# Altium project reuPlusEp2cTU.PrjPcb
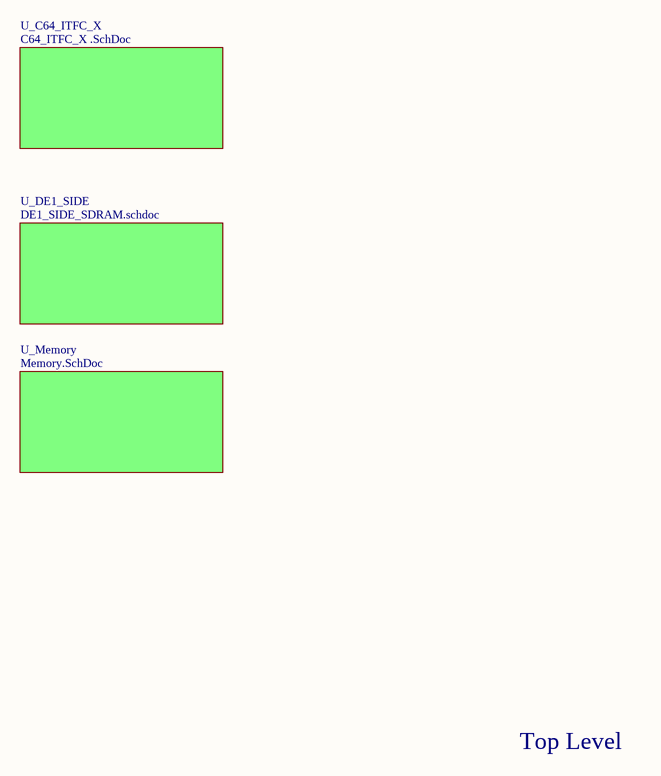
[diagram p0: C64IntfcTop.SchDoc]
4 sheets, 67 parts. Net scope: global (net labels, ports and power ports of the same name join across sheets).
Sheets:
  C64IntfcTop.SchDoc
    U_DE1_SIDE = DE1_SIDE_SDRAM.schdoc
    U_C64_ITFC_X = C64_ITFC_X .SchDoc
    U_Memory = Memory.SchDoc

## Sheet C64IntfcTop.SchDoc
size A; SheetNumber: 1; SheetTotal: 4

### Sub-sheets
U_C64_ITFC_X = C64_ITFC_X .SchDoc: no entries
U_DE1_SIDE = DE1_SIDE_SDRAM.schdoc: no entries
U_Memory = Memory.SchDoc: no entries

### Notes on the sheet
- Top Level

## Sheet DE1_SIDE_SDRAM.schdoc
size B; SheetNumber: 3; SheetTotal: 4
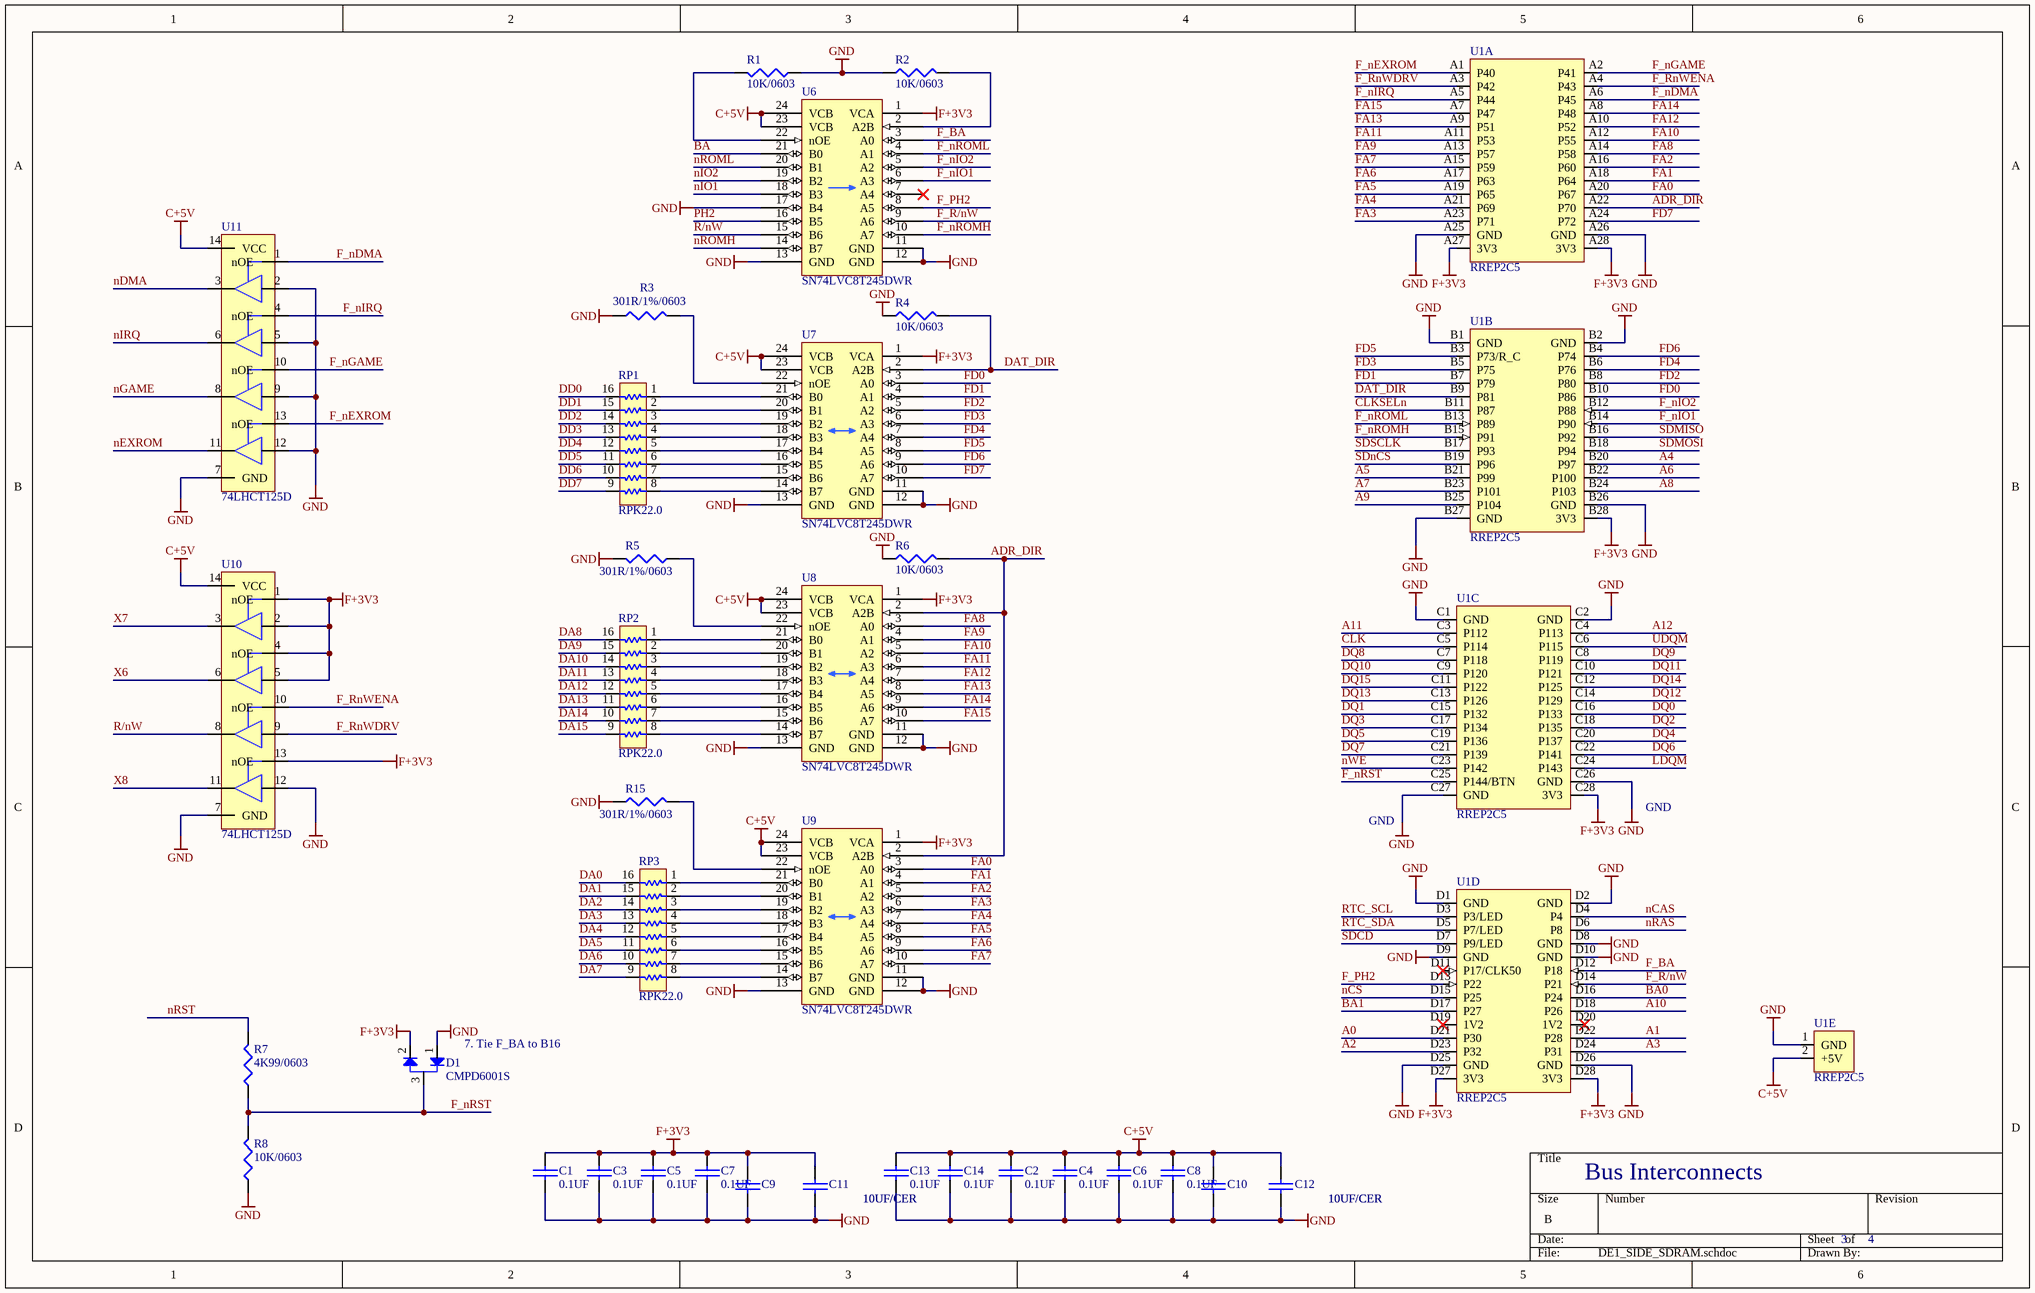
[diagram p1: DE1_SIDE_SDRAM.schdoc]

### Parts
C1  0.1UF  [0603]
C2  0.1UF  [0603]
C3  0.1UF  [0603]
C4  0.1UF  [0603]
C5  0.1UF  [0603]
C6  0.1UF  [0603]
C7  0.1UF  [0603]
C8  0.1UF  [0603]
C9  10UF/CER  [0805]
C10  10UF/CER  [0805]
C11  10UF/CER  [0805]
C12  10UF/CER  [0805]
C13  0.1UF  [0603]
C14  0.1UF  [0603]
D1  CMPD6001S  [SOT-23]
R1  10K/0603  [0603]
R2  10K/0603  [0603]
R3  301R/1%/0603  [0603]
R4  10K/0603  [0603]
R5  301R/1%/0603  [0603]
R6  10K/0603  [0603]
R7  4K99/0603  [0603]
R8  10K/0603  [0603]
R15  301R/1%/0603  [0603]
RP1  RPK22.0  [RPK4816]
RP2  RPK22.0  [RPK4816]
RP3  RPK22.0  [RPK4816]
U1  RREP2C5  [RR2C5]  (parts A,B,C,D,E of 5)
U6  SN74LVC8T245DWR  [SOL-24]
U7  SN74LVC8T245DWR  [SOL-24]
U8  SN74LVC8T245DWR  [SOL-24]
U9  SN74LVC8T245DWR  [SOL-24]
U10  74LHCT125D  [SOP14]
U11  74LHCT125D  [SOP14]

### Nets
C+5V: C2.1 C4.1 C6.1 C8.1 C10.2 C12.2 C13.1 C14.1 U1.2(+5V) U6.23(VCB) U6.24(VCB) U7.23(VCB) U7.24(VCB) U8.23(VCB) U8.24(VCB) U9.23(VCB) U9.24(VCB) U10.14(VCC) U11.14(VCC)
F+3V3: C1.1 C3.1 C5.1 C7.1 C9.2 C11.2 D1.2 U1.A27(3V3) U1.A28(3V3) U1.B28(3V3) U1.C28(3V3) U1.D27(3V3) U1.D28(3V3) U6.1(VCA) U7.1(VCA) U8.1(VCA) U9.1(VCA) U10.1(nOE) U10.2 U10.4(nOE) U10.5 U10.13(nOE)
GND: C1.2 C2.2 C3.2 C4.2 C5.2 C6.2 C7.2 C8.2 C9.1 C10.1 C11.1 C12.1 C13.2 C14.2 D1.1 R1.1 R2.1 R3.1 R4.1 R5.2 R6.1 R8.1 R15.1 U1.1(GND) U1.A25(GND) U1.A26(GND) U1.B1(GND) U1.B2(GND) U1.B26(GND) U1.B27(GND) U1.C1(GND) U1.C2(GND) U1.C26(GND) U1.C27(GND) U1.D1(GND) U1.D2(GND) U1.D8(GND) U1.D9(GND) U1.D10(GND) U1.D25(GND) U1.D26(GND) U6.11(GND) U6.12(GND) U6.13(GND) U6.17(B4) U7.11(GND) U7.12(GND) U7.13(GND) U8.11(GND) U8.12(GND) U8.13(GND) U9.11(GND) U9.12(GND) U9.13(GND) U10.7(GND) U10.12 U11.2 U11.5 U11.7(GND) U11.9 U11.12
A0: U1.D21(P30)
A1: U1.D22(P28)
A2: U1.D23(P32)
A3: U1.D24(P31)
A4: U1.B20(P97)
A5: U1.B21(P99)
A6: U1.B22(P100)
A7: U1.B23(P101)
A8: U1.B24(P103)
A9: U1.B25(P104)
A10: U1.D18(P26)
A11: U1.C3(P112)
A12: U1.C4(P113)
ADR_DIR: R6.2 U1.A22(P70) U8.2(A2B) U9.2(A2B)
BA: U6.21(B0)
BA0: U1.D16(P24)
BA1: U1.D17(P27)
CLK: U1.C5(P114)
CLKSELn: U1.B11(P87)
DA0: RP3.16
DA1: RP3.15
DA2: RP3.14
DA3: RP3.13
DA4: RP3.12
DA5: RP3.11
DA6: RP3.10
DA7: RP3.9
DA8: RP2.16
DA9: RP2.15
DA10: RP2.14
DA11: RP2.13
DA12: RP2.12
DA13: RP2.11
DA14: RP2.10
DA15: RP2.9
DAT_DIR: R4.2 U1.B9(P81) U7.2(A2B)
DD0: RP1.16
DD1: RP1.15
DD2: RP1.14
DD3: RP1.13
DD4: RP1.12
DD5: RP1.11
DD6: RP1.10
DD7: RP1.9
DQ0: U1.C16(P133)
DQ1: U1.C15(P132)
DQ2: U1.C18(P135)
DQ3: U1.C17(P134)
DQ4: U1.C20(P137)
DQ5: U1.C19(P136)
DQ6: U1.C22(P141)
DQ7: U1.C21(P139)
DQ8: U1.C7(P118)
DQ9: U1.C8(P119)
DQ10: U1.C9(P120)
DQ11: U1.C10(P121)
DQ12: U1.C14(P129)
DQ13: U1.C13(P126)
DQ14: U1.C12(P125)
DQ15: U1.C11(P122)
F_BA: U1.D12(P18) U6.3(A0)
F_nDMA: U1.A6(P45) U11.1(nOE)
F_nEXROM: U1.A1(P40) U11.13(nOE)
F_nGAME: U1.A2(P41) U11.10(nOE)
F_nIO1: U1.B14(P90) U6.6(A3)
F_nIO2: U1.B12(P88) U6.5(A2)
F_nIRQ: U1.A5(P44) U11.4(nOE)
F_nROMH: U1.B15(P91) U6.10(A7)
F_nROML: U1.B13(P89) U6.4(A1)
F_nRST: D1.3 R7.1 R8.2 U1.C25(P144/BTN)
F_PH2: U1.D13(P22) U6.8(A5)
F_R/nW: U1.D14(P21) U6.9(A6)
F_RnWDRV: U1.A3(P42) U10.9
F_RnWENA: U1.A4(P43) U10.10(nOE)
FA0: U1.A20(P67) U9.3(A0)
FA1: U1.A18(P64) U9.4(A1)
FA2: U1.A16(P60) U9.5(A2)
FA3: U1.A23(P71) U9.6(A3)
FA4: U1.A21(P69) U9.7(A4)
FA5: U1.A19(P65) U9.8(A5)
FA6: U1.A17(P63) U9.9(A6)
FA7: U1.A15(P59) U9.10(A7)
FA8: U1.A14(P58) U8.3(A0)
FA9: U1.A13(P57) U8.4(A1)
FA10: U1.A12(P55) U8.5(A2)
FA11: U1.A11(P53) U8.6(A3)
FA12: U1.A10(P52) U8.7(A4)
FA13: U1.A9(P51) U8.8(A5)
FA14: U1.A8(P48) U8.9(A6)
FA15: U1.A7(P47) U8.10(A7)
FD0: U1.B10(P86) U7.3(A0)
FD1: U1.B7(P79) U7.4(A1)
FD2: U1.B8(P80) U7.5(A2)
FD3: U1.B5(P75) U7.6(A3)
FD4: U1.B6(P76) U7.7(A4)
FD5: U1.B3(P73/R_C) U7.8(A5)
FD6: U1.B4(P74) U7.9(A6)
FD7: U1.A24(P72) U7.10(A7)
LDQM: U1.C24(P143)
nCAS: U1.D4(P4)
nCS: U1.D15(P25)
nDMA: U11.3
nEXROM: U11.11
nGAME: U11.8
nIO1: U6.18(B3)
nIO2: U6.19(B2)
nIRQ: U11.6
nRAS: U1.D6(P8)
nROMH: U6.14(B7)
nROML: U6.20(B1)
nRST: R7.2
nWE: U1.C23(P142)
PH2: U6.16(B5)
R/nW: U6.15(B6) U10.8
RTC_SCL: U1.D3(P3/LED)
RTC_SDA: U1.D5(P7/LED)
SDCD: U1.D7(P9/LED)
SDMISO: U1.B16(P92)
SDMOSI: U1.B18(P94)
SDnCS: U1.B19(P96)
SDSCLK: U1.B17(P93)
UDQM: U1.C6(P115)
X6: U10.6
X7: U10.3
X8: U10.11
NetR1_2: R1.2 U6.22(nOE)
NetR2_2: R2.2 U6.2(A2B)
NetR3_2: R3.2 U7.22(nOE)
NetR5_1: R5.1 U8.22(nOE)
NetR15_2: R15.2 U9.22(nOE)
NetRP1_1: RP1.1 U7.21(B0)
NetRP1_2: RP1.2 U7.20(B1)
NetRP1_3: RP1.3 U7.19(B2)
NetRP1_4: RP1.4 U7.18(B3)
NetRP1_5: RP1.5 U7.17(B4)
NetRP1_6: RP1.6 U7.16(B5)
NetRP1_7: RP1.7 U7.15(B6)
NetRP1_8: RP1.8 U7.14(B7)
NetRP2_1: RP2.1 U8.21(B0)
NetRP2_2: RP2.2 U8.20(B1)
NetRP2_3: RP2.3 U8.19(B2)
NetRP2_4: RP2.4 U8.18(B3)
NetRP2_5: RP2.5 U8.17(B4)
NetRP2_6: RP2.6 U8.16(B5)
NetRP2_7: RP2.7 U8.15(B6)
NetRP2_8: RP2.8 U8.14(B7)
NetRP3_1: RP3.1 U9.21(B0)
NetRP3_2: RP3.2 U9.20(B1)
NetRP3_3: RP3.3 U9.19(B2)
NetRP3_4: RP3.4 U9.18(B3)
NetRP3_5: RP3.5 U9.17(B4)
NetRP3_6: RP3.6 U9.16(B5)
NetRP3_7: RP3.7 U9.15(B6)
NetRP3_8: RP3.8 U9.14(B7)

Not connected (* = marked no-connect by the designer): U1 D11(P17/CLK50)* D19(1V2)* D20(1V2)*; U6 7(A4)*

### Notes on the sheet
- GND
- (near D1) 7. Tie F_BA to B16
- Bus Interconnects

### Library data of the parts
C1-C8 C13 C14 = 0.1UF: CAP .10UF 16V CERAMIC X7R 0603; MFG: Kemet; MFG PN: C0603C104K4RACTU; DK PN: 399-1096-1-ND
C9-C12 = 10UF/CER: 10µF ±10% 25V Ceramic Capacitor X7S 0805; Text Field1: Murata; Text Field2: GRM21BC71E106KE11L; Text Field3: 490-10496-1-ND
D1 = CMPD6001S: Diode Array 1 Pair Series Connection Standard 75V 250mA Surface Mount TO-236-3, SC-59, SOT-23-3; MFG PN: CMPD6001S TR; DK PN: CMPD6001S CT-ND; MFG: Central Semiconductor
R1 R2 R4 R6 R8 = 10K/0603: RES 10.0K OHM 1/10W 1% 0603 SMD; MFG: Dale/Vishay; MFG PN: CRCW060310K0FKEA; DK PN: 541-10.0KHCT-ND
R3 R5 R15 = 301R/1%/0603: 301 Ohms ±1% 0.1W, 1/10W Chip Resistor 0603 (1608 Metric) Moisture Resistant Thick Film; MFG: Yeago; MFG PN: RC0603FR-07301RL; DK PN: 311-301HRCT-ND
R7 = 4K99/0603: RES 4.99K OHM 1/10W 1% 0603 SMD; MFG: Dale/Vishay; MFG PN: CRCW06034K99FKEAC; DK PN: 541-3985-1-ND
RP1-RP3 = RPK22: 22 Ohm ±1Ohm 160mW Power Per Element Isolated Resistor Network/Array ±250ppm/°C 16-SOIC (0.220", 5.59mm Width); MFG: Bourns; MFG PN: 4816P-1-220LF; DK PN: 4816P-1-220LFCT-ND
U1 = RREP2C5: RioRand EP2C5T144 Altera Cyclone II FPGA Mini Development Board
U6-U9 = SN74LVC8T245DWR: Voltage Level Translator Bidirectional 1 Circuit 8 Channel 24-SOIC; MFG: TI; DK PN: 296-23280-1-ND
U10 U11 = 74LHCT125D: Buffer, Non-Inverting 4 Element 1 Bit per Element 3-State Output 14-SOIC; MFG: Nexpiria; MFG PN: 74HCT125D,653; DK PN: 1727-2834-2-ND

## Sheet C64_ITFC_X .SchDoc
size B; SheetNumber: 2; SheetTotal: 4
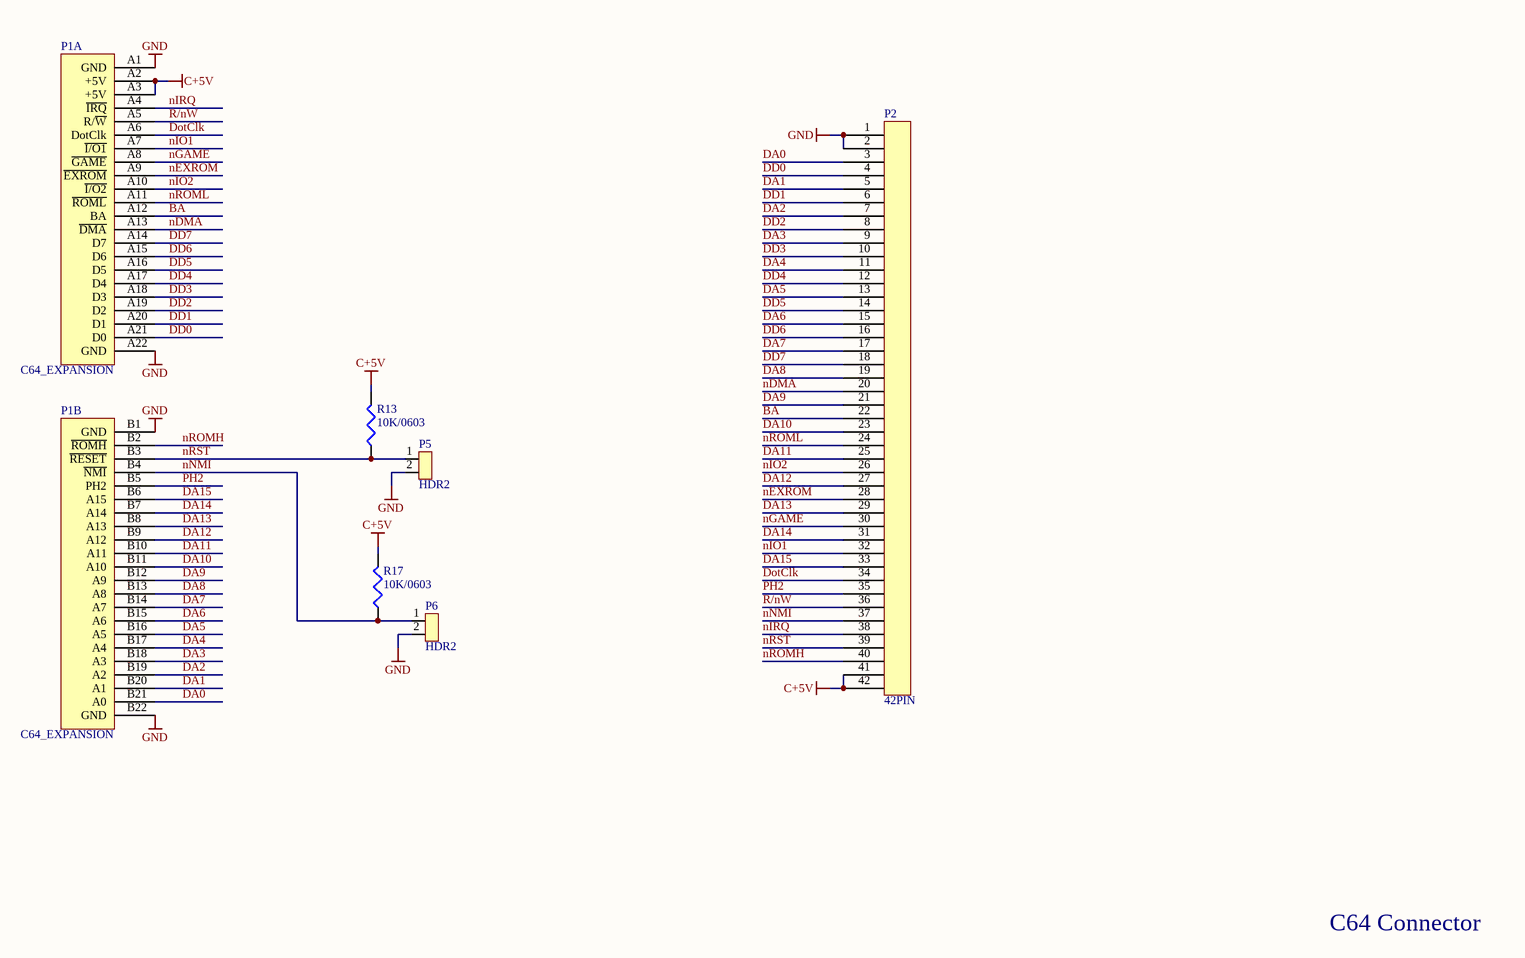
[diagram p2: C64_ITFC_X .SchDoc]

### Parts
P1  C64_EXPANSION  [C64_EXPANSION]  (parts A,B of 2)
P2  42PIN  [IDC42]
P5  HDR2  [HDR2]
P6  HDR2  [HDR2]
R13  10K/0603  [0603]
R17  10K/0603  [0603]

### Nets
C+5V: P1.A2(+5V) P1.A3(+5V) P2.41 P2.42 R13.2 R17.2
GND: P1.A1(GND) P1.A22(GND) P1.B1(GND) P1.B22(GND) P2.1 P2.2 P5.2 P6.2
BA: P1.A12(BA) P2.22
DA0: P1.B21(A0) P2.3
DA1: P1.B20(A1) P2.5
DA2: P1.B19(A2) P2.7
DA3: P1.B18(A3) P2.9
DA4: P1.B17(A4) P2.11
DA5: P1.B16(A5) P2.13
DA6: P1.B15(A6) P2.15
DA7: P1.B14(A7) P2.17
DA8: P1.B13(A8) P2.19
DA9: P1.B12(A9) P2.21
DA10: P1.B11(A10) P2.23
DA11: P1.B10(A11) P2.25
DA12: P1.B9(A12) P2.27
DA13: P1.B8(A13) P2.29
DA14: P1.B7(A14) P2.31
DA15: P1.B6(A15) P2.33
DD0: P1.A21(D0) P2.4
DD1: P1.A20(D1) P2.6
DD2: P1.A19(D2) P2.8
DD3: P1.A18(D3) P2.10
DD4: P1.A17(D4) P2.12
DD5: P1.A16(D5) P2.14
DD6: P1.A15(D6) P2.16
DD7: P1.A14(D7) P2.18
DotClk: P1.A6(DotClk) P2.34
nDMA: P1.A13(~{DMA}) P2.20
nEXROM: P1.A9(~{EXROM}) P2.28
nGAME: P1.A8(~{GAME}) P2.30
nIO1: P1.A7(~{I/O1}) P2.32
nIO2: P1.A10(~{I/O2}) P2.26
nIRQ: P1.A4(~{IRQ}) P2.38
nNMI: P1.B4(~{NMI}) P2.37 P6.1 R17.1
nROMH: P1.B2(~{ROMH}) P2.40
nROML: P1.A11(~{ROML}) P2.24
nRST: P1.B3(~{RESET}) P2.39 P5.1 R13.1
PH2: P1.B5(PH2) P2.35
R/nW: P1.A5(R/~{W}) P2.36

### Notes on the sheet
- C64 Connector

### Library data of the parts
P1 = C64_EXPANSION: C64 Expansion Connector
R13 R17 = 10K/0603: as R1 on sheet DE1_SIDE_SDRAM

## Sheet Memory.SchDoc
size B; SheetNumber: 4; SheetTotal: 4
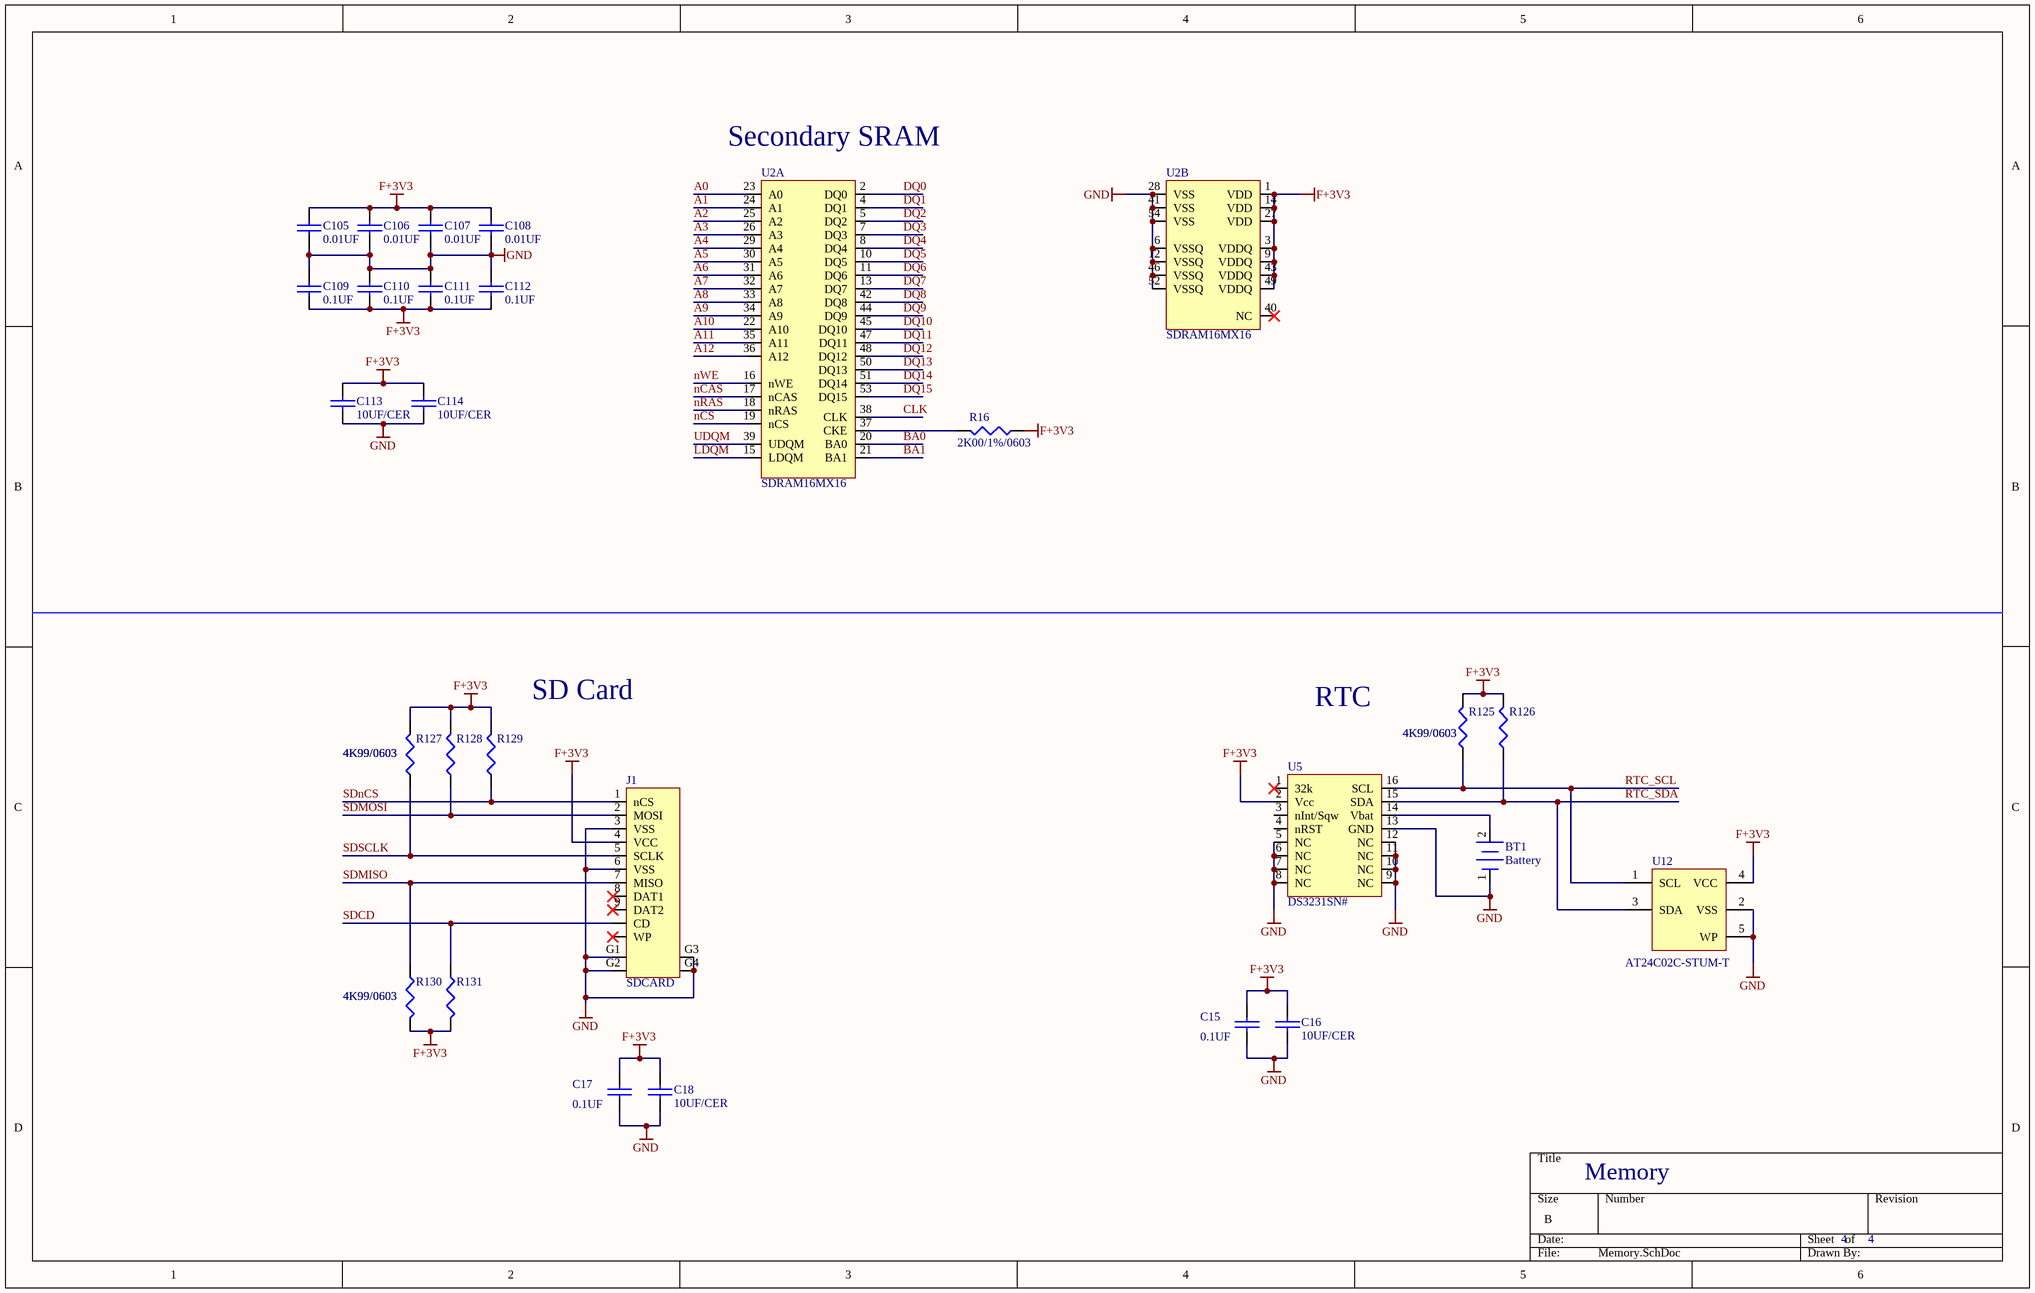
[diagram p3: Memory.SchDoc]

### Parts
BT1  Battery  [BC501SM]
C15  0.1UF  [0603]
C16  10UF/CER  [0805]
C17  0.1UF  [0603]
C18  10UF/CER  [0805]
C105  0.01UF  [0603]
C106  0.01UF  [0603]
C107  0.01UF  [0603]
C108  0.01UF  [0603]
C109  0.1UF  [0603]
C110  0.1UF  [0603]
C111  0.1UF  [0603]
C112  0.1UF  [0603]
C113  10UF/CER  [0805]
C114  10UF/CER  [0805]
J1  SDCARD  [SDCARD2041021]
R16  2K00/1%/0603  [0603]
R125  4K99/0603  [0603]
R126  4K99/0603  [0603]
R127  4K99/0603  [0603]
R128  4K99/0603  [0603]
R129  4K99/0603  [0603]
R130  4K99/0603  [0603]
R131  4K99/0603  [0603]
U2  SDRAM16MX16  [SOP54]  (parts A,B of 2)
U5  DS3231SN#  [SOL16]
U12  AT24C02C-STUM-T  [SOT23-5]

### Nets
F+3V3: C15.1 C16.1 C17.1 C18.1 C105.1 C106.1 C107.1 C108.1 C109.2 C110.2 C111.2 C112.2 C113.2 C114.2 J1.4(VCC) R16.1 R125.2 R126.2 R127.2 R128.2 R129.2 R130.2 R131.2 U2.1(VDD) U2.3(VDDQ) U2.9(VDDQ) U2.14(VDD) U2.27(VDD) U2.43(VDDQ) U2.49(VDDQ) U5.2(Vcc) U12.4(VCC)
GND: BT1.1 C15.2 C16.2 C17.2 C18.2 C105.2 C106.2 C107.2 C108.2 C109.1 C110.1 C111.1 C112.1 C113.1 C114.1 J1.3(VSS) J1.6(VSS) J1.G1 J1.G2 J1.G3 J1.G4 U2.6(VSSQ) U2.12(VSSQ) U2.28(VSS) U2.41(VSS) U2.46(VSSQ) U2.52(VSSQ) U2.54(VSS) U5.5(NC) U5.6(NC) U5.7(NC) U5.8(NC) U5.9(NC) U5.10(NC) U5.11(NC) U5.12(NC) U5.13(GND) U12.2(VSS) U12.5(WP)
A0: U2.23(A0)
A1: U2.24(A1)
A2: U2.25(A2)
A3: U2.26(A3)
A4: U2.29(A4)
A5: U2.30(A5)
A6: U2.31(A6)
A7: U2.32(A7)
A8: U2.33(A8)
A9: U2.34(A9)
A10: U2.22(A10)
A11: U2.35(A11)
A12: U2.36(A12)
BA0: U2.20(BA0)
BA1: U2.21(BA1)
CLK: U2.38(CLK)
DQ0: U2.2(DQ0)
DQ1: U2.4(DQ1)
DQ2: U2.5(DQ2)
DQ3: U2.7(DQ3)
DQ4: U2.8(DQ4)
DQ5: U2.10(DQ5)
DQ6: U2.11(DQ6)
DQ7: U2.13(DQ7)
DQ8: U2.42(DQ8)
DQ9: U2.44(DQ9)
DQ10: U2.45(DQ10)
DQ11: U2.47(DQ11)
DQ12: U2.48(DQ12)
DQ13: U2.50(DQ13)
DQ14: U2.51(DQ14)
DQ15: U2.53(DQ15)
LDQM: U2.15(LDQM)
nCAS: U2.17(nCAS)
nCS: U2.19(nCS)
nRAS: U2.18(nRAS)
nWE: U2.16(nWE)
RTC_SCL: R125.1 U5.16(SCL) U12.1(SCL)
RTC_SDA: R126.1 U5.15(SDA) U12.3(SDA)
SDCD: J1.CD R131.1
SDMISO: J1.7(MISO) R130.1
SDMOSI: J1.2(MOSI) R128.1
SDnCS: J1.1(nCS) R129.1
SDSCLK: J1.5(SCLK) R127.1
UDQM: U2.39(UDQM)
NetBT1_2: BT1.2 U5.14(Vbat)
NetR16_2: R16.2 U2.37(CKE)

Not connected (* = marked no-connect by the designer): J1 8(DAT1)* 9(DAT2)* WP*; U2 40(NC)*; U5 1(32k)* 3(nInt/Sqw) 4(nRST)

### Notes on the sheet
- (near U2) Secondary SRAM
- (near R129) SD Card
- RTC
- Memory

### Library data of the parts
BT1 = BC501SM-TR: Battery Holder (Open) Coin, 12.0mm 1 Cell SMD (SMT) Tab; MFG: MPD; DK PN: BC501SM-TR-ND
C15 C17 C109-C112 = 0.1UF: as C1 on sheet DE1_SIDE_SDRAM
C16 C18 = 10UF/CER: 10µF ±10% 25V Ceramic Capacitor X7S 0805; MFG: Murata; MFG PN: GRM21BC71E106KE11L; DK PN: 490-10496-1-ND
C105-C108 = 0.01UF: 10000pF ±10% 10V Ceramic Capacitor X7R 0603 (1608 Metric); MFG: Kemet; MFG PN: C0603C103K8RACTU; DK PN: 399-11132-1-ND
C113 C114 = 10UF/CER: as C9 on sheet DE1_SIDE_SDRAM
J1 = SDCARD: 11 (9 + 2) Position Card Connector Secure Digital - SD Surface Mount, Right Angle Gold; MFG: TE; MFG PN: 2041021-4; DK PN: A101492CT-ND
R16 = 2K00/1%/0603: 2 kOhms ±1% 0.1W, 1/10W Chip Resistor 0603 (1608 Metric) Moisture Resistant Thick Film; MFG: Yeago; MFG PN: RC0603FR-072KL; DK PN: 311-2.00KHRCT-ND
R125-R131 = 4K99/0603: as R7 on sheet DE1_SIDE_SDRAM
U2 = SDRAM16MX16: SDRAM Memory IC 256Mb (16M x 16) Parallel 166MHz 5ns 54-TSOP II; MFG: Winbond; MFG PN: W9825G6KH-6; DK PN: W9825G6KH-6-ND
U5 = DS3231SN#: Real Time Clock (RTC) IC Clock/Calendar I²C, 2-Wire Serial 16-SOIC (0.295", 7.50mm Width); MFG: Maxim; DK PN: DS3231SN#-ND
U12 = AT24C02C-STUM-T: IC EEPROM 2KBIT I2C 1MHZ SOT23-5; MFG: Microchip; DK PN: AT24C02C-STUM-TCT-ND - Cut Tape (CT)

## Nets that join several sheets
C+5V: DE1_SIDE_SDRAM (19 pins), C64_ITFC_X  (6 pins)
F+3V3: DE1_SIDE_SDRAM (22 pins), Memory (32 pins)
GND: DE1_SIDE_SDRAM (61 pins), C64_ITFC_X  (8 pins), Memory (39 pins)
A0: DE1_SIDE_SDRAM (U1.D21), Memory (U2.23)
A1: DE1_SIDE_SDRAM (U1.D22), Memory (U2.24)
A2: DE1_SIDE_SDRAM (U1.D23), Memory (U2.25)
A3: DE1_SIDE_SDRAM (U1.D24), Memory (U2.26)
A4: DE1_SIDE_SDRAM (U1.B20), Memory (U2.29)
A5: DE1_SIDE_SDRAM (U1.B21), Memory (U2.30)
A6: DE1_SIDE_SDRAM (U1.B22), Memory (U2.31)
A7: DE1_SIDE_SDRAM (U1.B23), Memory (U2.32)
A8: DE1_SIDE_SDRAM (U1.B24), Memory (U2.33)
A9: DE1_SIDE_SDRAM (U1.B25), Memory (U2.34)
A10: DE1_SIDE_SDRAM (U1.D18), Memory (U2.22)
A11: DE1_SIDE_SDRAM (U1.C3), Memory (U2.35)
A12: DE1_SIDE_SDRAM (U1.C4), Memory (U2.36)
BA: DE1_SIDE_SDRAM (U6.21), C64_ITFC_X  (P1.A12 P2.22)
BA0: DE1_SIDE_SDRAM (U1.D16), Memory (U2.20)
BA1: DE1_SIDE_SDRAM (U1.D17), Memory (U2.21)
CLK: DE1_SIDE_SDRAM (U1.C5), Memory (U2.38)
DA0: DE1_SIDE_SDRAM (RP3.16), C64_ITFC_X  (P1.B21 P2.3)
DA1: DE1_SIDE_SDRAM (RP3.15), C64_ITFC_X  (P1.B20 P2.5)
DA2: DE1_SIDE_SDRAM (RP3.14), C64_ITFC_X  (P1.B19 P2.7)
DA3: DE1_SIDE_SDRAM (RP3.13), C64_ITFC_X  (P1.B18 P2.9)
DA4: DE1_SIDE_SDRAM (RP3.12), C64_ITFC_X  (P1.B17 P2.11)
DA5: DE1_SIDE_SDRAM (RP3.11), C64_ITFC_X  (P1.B16 P2.13)
DA6: DE1_SIDE_SDRAM (RP3.10), C64_ITFC_X  (P1.B15 P2.15)
DA7: DE1_SIDE_SDRAM (RP3.9), C64_ITFC_X  (P1.B14 P2.17)
DA8: DE1_SIDE_SDRAM (RP2.16), C64_ITFC_X  (P1.B13 P2.19)
DA9: DE1_SIDE_SDRAM (RP2.15), C64_ITFC_X  (P1.B12 P2.21)
DA10: DE1_SIDE_SDRAM (RP2.14), C64_ITFC_X  (P1.B11 P2.23)
DA11: DE1_SIDE_SDRAM (RP2.13), C64_ITFC_X  (P1.B10 P2.25)
DA12: DE1_SIDE_SDRAM (RP2.12), C64_ITFC_X  (P1.B9 P2.27)
DA13: DE1_SIDE_SDRAM (RP2.11), C64_ITFC_X  (P1.B8 P2.29)
DA14: DE1_SIDE_SDRAM (RP2.10), C64_ITFC_X  (P1.B7 P2.31)
DA15: DE1_SIDE_SDRAM (RP2.9), C64_ITFC_X  (P1.B6 P2.33)
DD0: DE1_SIDE_SDRAM (RP1.16), C64_ITFC_X  (P1.A21 P2.4)
DD1: DE1_SIDE_SDRAM (RP1.15), C64_ITFC_X  (P1.A20 P2.6)
DD2: DE1_SIDE_SDRAM (RP1.14), C64_ITFC_X  (P1.A19 P2.8)
DD3: DE1_SIDE_SDRAM (RP1.13), C64_ITFC_X  (P1.A18 P2.10)
DD4: DE1_SIDE_SDRAM (RP1.12), C64_ITFC_X  (P1.A17 P2.12)
DD5: DE1_SIDE_SDRAM (RP1.11), C64_ITFC_X  (P1.A16 P2.14)
DD6: DE1_SIDE_SDRAM (RP1.10), C64_ITFC_X  (P1.A15 P2.16)
DD7: DE1_SIDE_SDRAM (RP1.9), C64_ITFC_X  (P1.A14 P2.18)
DQ0: DE1_SIDE_SDRAM (U1.C16), Memory (U2.2)
DQ1: DE1_SIDE_SDRAM (U1.C15), Memory (U2.4)
DQ2: DE1_SIDE_SDRAM (U1.C18), Memory (U2.5)
DQ3: DE1_SIDE_SDRAM (U1.C17), Memory (U2.7)
DQ4: DE1_SIDE_SDRAM (U1.C20), Memory (U2.8)
DQ5: DE1_SIDE_SDRAM (U1.C19), Memory (U2.10)
DQ6: DE1_SIDE_SDRAM (U1.C22), Memory (U2.11)
DQ7: DE1_SIDE_SDRAM (U1.C21), Memory (U2.13)
DQ8: DE1_SIDE_SDRAM (U1.C7), Memory (U2.42)
DQ9: DE1_SIDE_SDRAM (U1.C8), Memory (U2.44)
DQ10: DE1_SIDE_SDRAM (U1.C9), Memory (U2.45)
DQ11: DE1_SIDE_SDRAM (U1.C10), Memory (U2.47)
DQ12: DE1_SIDE_SDRAM (U1.C14), Memory (U2.48)
DQ13: DE1_SIDE_SDRAM (U1.C13), Memory (U2.50)
DQ14: DE1_SIDE_SDRAM (U1.C12), Memory (U2.51)
DQ15: DE1_SIDE_SDRAM (U1.C11), Memory (U2.53)
LDQM: DE1_SIDE_SDRAM (U1.C24), Memory (U2.15)
nCAS: DE1_SIDE_SDRAM (U1.D4), Memory (U2.17)
nCS: DE1_SIDE_SDRAM (U1.D15), Memory (U2.19)
nDMA: DE1_SIDE_SDRAM (U11.3), C64_ITFC_X  (P1.A13 P2.20)
nEXROM: DE1_SIDE_SDRAM (U11.11), C64_ITFC_X  (P1.A9 P2.28)
nGAME: DE1_SIDE_SDRAM (U11.8), C64_ITFC_X  (P1.A8 P2.30)
nIO1: DE1_SIDE_SDRAM (U6.18), C64_ITFC_X  (P1.A7 P2.32)
nIO2: DE1_SIDE_SDRAM (U6.19), C64_ITFC_X  (P1.A10 P2.26)
nIRQ: DE1_SIDE_SDRAM (U11.6), C64_ITFC_X  (P1.A4 P2.38)
nRAS: DE1_SIDE_SDRAM (U1.D6), Memory (U2.18)
nROMH: DE1_SIDE_SDRAM (U6.14), C64_ITFC_X  (P1.B2 P2.40)
nROML: DE1_SIDE_SDRAM (U6.20), C64_ITFC_X  (P1.A11 P2.24)
nRST: DE1_SIDE_SDRAM (R7.2), C64_ITFC_X  (P1.B3 P2.39 P5.1 R13.1)
nWE: DE1_SIDE_SDRAM (U1.C23), Memory (U2.16)
PH2: DE1_SIDE_SDRAM (U6.16), C64_ITFC_X  (P1.B5 P2.35)
R/nW: DE1_SIDE_SDRAM (U6.15 U10.8), C64_ITFC_X  (P1.A5 P2.36)
RTC_SCL: DE1_SIDE_SDRAM (U1.D3), Memory (R125.1 U5.16 U12.1)
RTC_SDA: DE1_SIDE_SDRAM (U1.D5), Memory (R126.1 U5.15 U12.3)
SDCD: DE1_SIDE_SDRAM (U1.D7), Memory (J1.CD R131.1)
SDMISO: DE1_SIDE_SDRAM (U1.B16), Memory (J1.7 R130.1)
SDMOSI: DE1_SIDE_SDRAM (U1.B18), Memory (J1.2 R128.1)
SDnCS: DE1_SIDE_SDRAM (U1.B19), Memory (J1.1 R129.1)
SDSCLK: DE1_SIDE_SDRAM (U1.B17), Memory (J1.5 R127.1)
UDQM: DE1_SIDE_SDRAM (U1.C6), Memory (U2.39)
